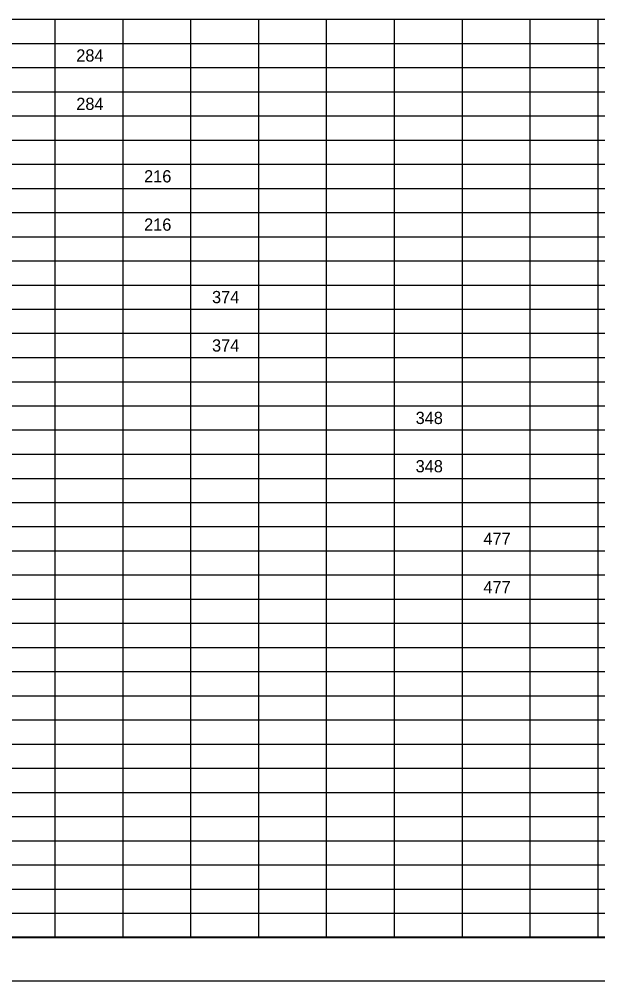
# Model space of a CAD drawing. Extents: x 0.2 to 34.2, y 0 to 22.
# Drawn here: x 6.82 to 13.45, y 0.03 to 11.04 of the extents above; entities that cross this region are included whole.
import ezdxf

# ---------------------------------------------------------------- set-up
doc = ezdxf.new("R2010")
doc.units = 0
for name, color, linetype in [('Default', 7, 'Continuous'), ('SH_Border', 7, 'Continuous'), ('SH_Cut_Line', 7, 'Continuous')]:
    doc.layers.add(name, color=color, linetype=linetype)

msp = doc.modelspace()

# ---------------------------------------------------------------- linework, layer by layer
at = {"layer": 'Default'}
for p, q in [((4.894, 11.037), (8.004, 11.037)), ((7.226, 11.037), (7.226, 10.76)), ((8.004, 11.037), (8.781, 11.037)), ((8.004, 11.037), (8.004, 10.76)), ((8.781, 11.037), (13.445, 11.037)), ((8.781, 11.037), (8.781, 10.76)), ((9.558, 11.037), (9.558, 10.76)), ((10.336, 11.037), (10.336, 10.76)), ((11.113, 11.037), (11.113, 10.76)), ((11.891, 11.037), (11.891, 10.76)), ((12.668, 11.037), (12.668, 10.76)), ((13.445, 11.037), (14.223, 11.037)), ((13.445, 11.037), (13.445, 10.76)), ((4.894, 10.76), (8.004, 10.76)), ((7.226, 10.76), (7.226, 10.483)), ((8.004, 10.76), (8.781, 10.76)), ((8.004, 10.76), (8.004, 10.483)), ((8.781, 10.76), (13.445, 10.76)), ((8.781, 10.76), (8.781, 10.483)), ((9.558, 10.76), (9.558, 10.483)), ((10.336, 10.76), (10.336, 10.483)), ((11.113, 10.76), (11.113, 10.483)), ((11.891, 10.76), (11.891, 10.483)), ((12.668, 10.76), (12.668, 10.483)), ((13.445, 10.76), (14.223, 10.76)), ((13.445, 10.76), (13.445, 10.483)), ((4.894, 10.483), (8.004, 10.483)), ((7.226, 10.483), (7.226, 10.207)), ((8.004, 10.483), (8.781, 10.483)), ((8.004, 10.483), (8.004, 10.207)), ((8.781, 10.483), (13.445, 10.483)), ((8.781, 10.483), (8.781, 10.207)), ((9.558, 10.483), (9.558, 10.207)), ((10.336, 10.483), (10.336, 10.207)), ((11.113, 10.483), (11.113, 10.207)), ((11.891, 10.483), (11.891, 10.207)), ((12.668, 10.483), (12.668, 10.207)), ((13.445, 10.483), (14.223, 10.483)), ((13.445, 10.483), (13.445, 10.207)), ((4.894, 10.207), (8.004, 10.207)), ((7.226, 10.207), (7.226, 9.93)), ((8.004, 10.207), (8.781, 10.207)), ((8.004, 10.207), (8.004, 9.93)), ((8.781, 10.207), (13.445, 10.207)), ((8.781, 10.207), (8.781, 9.93)), ((9.558, 10.207), (9.558, 9.93)), ((10.336, 10.207), (10.336, 9.93)), ((11.113, 10.207), (11.113, 9.93)), ((11.891, 10.207), (11.891, 9.93)), ((12.668, 10.207), (12.668, 9.93)), ((13.445, 10.207), (14.223, 10.207)), ((13.445, 10.207), (13.445, 9.93)), ((4.894, 9.93), (8.004, 9.93)), ((7.226, 9.93), (7.226, 9.653)), ((8.004, 9.93), (8.781, 9.93)), ((8.004, 9.93), (8.004, 9.653)), ((8.781, 9.93), (13.445, 9.93)), ((8.781, 9.93), (8.781, 9.653)), ((9.558, 9.93), (9.558, 9.653)), ((10.336, 9.93), (10.336, 9.653)), ((11.113, 9.93), (11.113, 9.653)), ((11.891, 9.93), (11.891, 9.653)), ((12.668, 9.93), (12.668, 9.653)), ((13.445, 9.93), (14.223, 9.93)), ((13.445, 9.93), (13.445, 9.653)), ((4.894, 9.653), (8.004, 9.653)), ((7.226, 9.653), (7.226, 9.377)), ((8.004, 9.653), (8.781, 9.653)), ((8.004, 9.653), (8.004, 9.377)), ((8.781, 9.653), (13.445, 9.653)), ((8.781, 9.653), (8.781, 9.377)), ((9.558, 9.653), (9.558, 9.377)), ((10.336, 9.653), (10.336, 9.377)), ((11.113, 9.653), (11.113, 9.377)), ((11.891, 9.653), (11.891, 9.377)), ((12.668, 9.653), (12.668, 9.377)), ((13.445, 9.653), (14.223, 9.653)), ((13.445, 9.653), (13.445, 9.377)), ((4.894, 9.377), (8.004, 9.377)), ((7.226, 9.377), (7.226, 9.1)), ((8.004, 9.377), (8.781, 9.377)), ((8.004, 9.377), (8.004, 9.1)), ((8.781, 9.377), (13.445, 9.377)), ((8.781, 9.377), (8.781, 9.1)), ((9.558, 9.377), (9.558, 9.1)), ((10.336, 9.377), (10.336, 9.1)), ((11.113, 9.377), (11.113, 9.1)), ((11.891, 9.377), (11.891, 9.1)), ((12.668, 9.377), (12.668, 9.1)), ((13.445, 9.377), (14.223, 9.377)), ((13.445, 9.377), (13.445, 9.1)), ((4.894, 9.1), (8.004, 9.1)), ((7.226, 9.1), (7.226, 8.823)), ((8.004, 9.1), (8.781, 9.1)), ((8.004, 9.1), (8.004, 8.823)), ((8.781, 9.1), (13.445, 9.1)), ((8.781, 9.1), (8.781, 8.823)), ((9.558, 9.1), (9.558, 8.823)), ((10.336, 9.1), (10.336, 8.823)), ((11.113, 9.1), (11.113, 8.823)), ((11.891, 9.1), (11.891, 8.823)), ((12.668, 9.1), (12.668, 8.823)), ((13.445, 9.1), (14.223, 9.1)), ((13.445, 9.1), (13.445, 8.823)), ((4.894, 8.823), (8.004, 8.823)), ((7.226, 8.823), (7.226, 8.546)), ((8.004, 8.823), (8.781, 8.823)), ((8.004, 8.823), (8.004, 8.546)), ((8.781, 8.823), (13.445, 8.823)), ((8.781, 8.823), (8.781, 8.546)), ((9.558, 8.823), (9.558, 8.546)), ((10.336, 8.823), (10.336, 8.546)), ((11.113, 8.823), (11.113, 8.546)), ((11.891, 8.823), (11.891, 8.546)), ((12.668, 8.823), (12.668, 8.546)), ((13.445, 8.823), (14.223, 8.823)), ((13.445, 8.823), (13.445, 8.546)), ((4.894, 8.546), (8.004, 8.546)), ((7.226, 8.546), (7.226, 8.27)), ((8.004, 8.546), (8.781, 8.546)), ((8.004, 8.546), (8.004, 8.27)), ((8.781, 8.546), (13.445, 8.546)), ((8.781, 8.546), (8.781, 8.27)), ((9.558, 8.546), (9.558, 8.27)), ((10.336, 8.546), (10.336, 8.27)), ((11.113, 8.546), (11.113, 8.27)), ((11.891, 8.546), (11.891, 8.27)), ((12.668, 8.546), (12.668, 8.27)), ((13.445, 8.546), (14.223, 8.546)), ((13.445, 8.546), (13.445, 8.27)), ((4.894, 8.27), (8.004, 8.27)), ((7.226, 8.27), (7.226, 7.993)), ((8.004, 8.27), (8.781, 8.27)), ((8.004, 8.27), (8.004, 7.993)), ((8.781, 8.27), (13.445, 8.27)), ((8.781, 8.27), (8.781, 7.993)), ((9.558, 8.27), (9.558, 7.993)), ((10.336, 8.27), (10.336, 7.993)), ((11.113, 8.27), (11.113, 7.993)), ((11.891, 8.27), (11.891, 7.993)), ((12.668, 8.27), (12.668, 7.993)), ((13.445, 8.27), (14.223, 8.27)), ((13.445, 8.27), (13.445, 7.993)), ((4.894, 7.993), (8.004, 7.993)), ((7.226, 7.993), (7.226, 7.716)), ((8.004, 7.993), (8.781, 7.993)), ((8.004, 7.993), (8.004, 7.716)), ((8.781, 7.993), (13.445, 7.993)), ((8.781, 7.993), (8.781, 7.716)), ((9.558, 7.993), (9.558, 7.716)), ((10.336, 7.993), (10.336, 7.716)), ((11.113, 7.993), (11.113, 7.716)), ((11.891, 7.993), (11.891, 7.716)), ((12.668, 7.993), (12.668, 7.716)), ((13.445, 7.993), (14.223, 7.993)), ((13.445, 7.993), (13.445, 7.716)), ((4.894, 7.716), (8.004, 7.716)), ((7.226, 7.716), (7.226, 7.44)), ((8.004, 7.716), (8.781, 7.716)), ((8.004, 7.716), (8.004, 7.44)), ((8.781, 7.716), (13.445, 7.716)), ((8.781, 7.716), (8.781, 7.44)), ((9.558, 7.716), (9.558, 7.44)), ((10.336, 7.716), (10.336, 7.44)), ((11.113, 7.716), (11.113, 7.44)), ((11.891, 7.716), (11.891, 7.44)), ((12.668, 7.716), (12.668, 7.44)), ((13.445, 7.716), (14.223, 7.716)), ((13.445, 7.716), (13.445, 7.44)), ((4.894, 7.44), (8.004, 7.44)), ((7.226, 7.44), (7.226, 7.163)), ((8.004, 7.44), (8.781, 7.44)), ((8.004, 7.44), (8.004, 7.163)), ((8.781, 7.44), (13.445, 7.44)), ((8.781, 7.44), (8.781, 7.163)), ((9.558, 7.44), (9.558, 7.163)), ((10.336, 7.44), (10.336, 7.163)), ((11.113, 7.44), (11.113, 7.163)), ((11.891, 7.44), (11.891, 7.163)), ((12.668, 7.44), (12.668, 7.163)), ((13.445, 7.44), (14.223, 7.44)), ((13.445, 7.44), (13.445, 7.163)), ((4.894, 7.163), (8.004, 7.163)), ((7.226, 7.163), (7.226, 6.886)), ((8.004, 7.163), (8.781, 7.163)), ((8.004, 7.163), (8.004, 6.886)), ((8.781, 7.163), (13.445, 7.163)), ((8.781, 7.163), (8.781, 6.886)), ((9.558, 7.163), (9.558, 6.886)), ((10.336, 7.163), (10.336, 6.886)), ((11.113, 7.163), (11.113, 6.886)), ((11.891, 7.163), (11.891, 6.886)), ((12.668, 7.163), (12.668, 6.886)), ((13.445, 7.163), (14.223, 7.163)), ((13.445, 7.163), (13.445, 6.886)), ((4.894, 6.886), (8.004, 6.886)), ((7.226, 6.886), (7.226, 6.609)), ((8.004, 6.886), (8.781, 6.886)), ((8.004, 6.886), (8.004, 6.609)), ((8.781, 6.886), (13.445, 6.886)), ((8.781, 6.886), (8.781, 6.609)), ((9.558, 6.886), (9.558, 6.609)), ((10.336, 6.886), (10.336, 6.609)), ((11.113, 6.886), (11.113, 6.609)), ((11.891, 6.886), (11.891, 6.609)), ((12.668, 6.886), (12.668, 6.609)), ((13.445, 6.886), (14.223, 6.886)), ((13.445, 6.886), (13.445, 6.609)), ((4.894, 6.609), (8.004, 6.609)), ((7.226, 6.609), (7.226, 6.333)), ((8.004, 6.609), (8.781, 6.609)), ((8.004, 6.609), (8.004, 6.333)), ((8.781, 6.609), (13.445, 6.609)), ((8.781, 6.609), (8.781, 6.333)), ((9.558, 6.609), (9.558, 6.333)), ((10.336, 6.609), (10.336, 6.333)), ((11.113, 6.609), (11.113, 6.333)), ((11.891, 6.609), (11.891, 6.333)), ((12.668, 6.609), (12.668, 6.333)), ((13.445, 6.609), (14.223, 6.609)), ((13.445, 6.609), (13.445, 6.333)), ((4.894, 6.333), (8.004, 6.333)), ((7.226, 6.333), (7.226, 5.779)), ((8.004, 6.333), (8.781, 6.333)), ((8.004, 6.333), (8.004, 5.779)), ((8.781, 6.333), (13.445, 6.333)), ((8.781, 6.333), (8.781, 5.779)), ((9.558, 6.333), (9.558, 5.779)), ((10.336, 6.333), (10.336, 5.779)), ((11.113, 6.333), (11.113, 5.779)), ((11.891, 6.333), (11.891, 5.779)), ((12.668, 6.333), (12.668, 5.779)), ((13.445, 6.333), (14.223, 6.333)), ((13.445, 6.333), (13.445, 5.779)), ((4.894, 6.056), (8.004, 6.056)), ((8.004, 6.056), (8.781, 6.056)), ((8.781, 6.056), (13.445, 6.056)), ((13.445, 6.056), (14.223, 6.056)), ((4.894, 5.779), (8.004, 5.779)), ((7.226, 5.779), (7.226, 5.503)), ((8.004, 5.779), (8.781, 5.779)), ((8.004, 5.779), (8.004, 5.503)), ((8.781, 5.779), (13.445, 5.779)), ((8.781, 5.779), (8.781, 5.503)), ((9.558, 5.779), (9.558, 5.503)), ((10.336, 5.779), (10.336, 5.503)), ((11.113, 5.779), (11.113, 5.503)), ((11.891, 5.779), (11.891, 5.503)), ((12.668, 5.779), (12.668, 5.503)), ((13.445, 5.779), (14.223, 5.779)), ((13.445, 5.779), (13.445, 5.503)), ((4.894, 5.503), (8.004, 5.503)), ((7.226, 5.503), (7.226, 4.396)), ((8.004, 5.503), (8.781, 5.503)), ((8.004, 5.503), (8.004, 4.396)), ((8.781, 5.503), (13.445, 5.503)), ((8.781, 5.503), (8.781, 4.396)), ((9.558, 5.503), (9.558, 4.396)), ((10.336, 5.503), (10.336, 4.396)), ((11.113, 5.503), (11.113, 4.396)), ((11.891, 5.503), (11.891, 4.396)), ((12.668, 5.503), (12.668, 4.396)), ((13.445, 5.503), (14.223, 5.503)), ((13.445, 5.503), (13.445, 4.396)), ((4.894, 5.226), (8.004, 5.226)), ((8.004, 5.226), (8.781, 5.226)), ((8.781, 5.226), (13.445, 5.226)), ((13.445, 5.226), (14.223, 5.226)), ((4.894, 4.949), (8.004, 4.949)), ((8.004, 4.949), (8.781, 4.949)), ((8.781, 4.949), (13.445, 4.949)), ((13.445, 4.949), (14.223, 4.949)), ((4.894, 4.673), (8.004, 4.673)), ((8.004, 4.673), (8.781, 4.673)), ((8.781, 4.673), (13.445, 4.673)), ((13.445, 4.673), (14.223, 4.673)), ((4.894, 4.396), (8.004, 4.396)), ((7.226, 4.396), (7.226, 4.119)), ((8.004, 4.396), (8.781, 4.396)), ((8.004, 4.396), (8.004, 4.119)), ((8.781, 4.396), (13.445, 4.396)), ((8.781, 4.396), (8.781, 4.119)), ((9.558, 4.396), (9.558, 4.119)), ((10.336, 4.396), (10.336, 4.119)), ((11.113, 4.396), (11.113, 4.119)), ((11.891, 4.396), (11.891, 4.119)), ((12.668, 4.396), (12.668, 4.119)), ((13.445, 4.396), (14.223, 4.396)), ((13.445, 4.396), (13.445, 4.119)), ((4.894, 4.119), (8.004, 4.119)), ((7.226, 4.119), (7.226, 3.012)), ((8.004, 4.119), (8.781, 4.119)), ((8.004, 4.119), (8.004, 3.012)), ((8.781, 4.119), (13.445, 4.119)), ((8.781, 4.119), (8.781, 3.012)), ((9.558, 4.119), (9.558, 3.012)), ((10.336, 4.119), (10.336, 3.012)), ((11.113, 4.119), (11.113, 3.012)), ((11.891, 4.119), (11.891, 3.012)), ((12.668, 4.119), (12.668, 3.012)), ((13.445, 4.119), (14.223, 4.119)), ((13.445, 4.119), (13.445, 3.012)), ((4.894, 3.842), (8.004, 3.842)), ((8.004, 3.842), (8.781, 3.842)), ((8.781, 3.842), (13.445, 3.842)), ((13.445, 3.842), (14.223, 3.842)), ((4.894, 3.566), (8.004, 3.566)), ((8.004, 3.566), (8.781, 3.566)), ((8.781, 3.566), (13.445, 3.566)), ((13.445, 3.566), (14.223, 3.566)), ((4.894, 3.289), (8.004, 3.289)), ((8.004, 3.289), (8.781, 3.289)), ((8.781, 3.289), (13.445, 3.289)), ((13.445, 3.289), (14.223, 3.289)), ((4.894, 3.012), (8.004, 3.012)), ((7.226, 3.012), (7.226, 2.736)), ((8.004, 3.012), (8.781, 3.012)), ((8.004, 3.012), (8.004, 2.736)), ((8.781, 3.012), (13.445, 3.012)), ((8.781, 3.012), (8.781, 2.736)), ((9.558, 3.012), (9.558, 2.736)), ((10.336, 3.012), (10.336, 2.736)), ((11.113, 3.012), (11.113, 2.736)), ((11.891, 3.012), (11.891, 2.736)), ((12.668, 3.012), (12.668, 2.736)), ((13.445, 3.012), (14.223, 3.012)), ((13.445, 3.012), (13.445, 2.736)), ((4.894, 2.736), (8.004, 2.736)), ((7.226, 2.736), (7.226, 1.629)), ((8.004, 2.736), (8.781, 2.736)), ((8.004, 2.736), (8.004, 1.629)), ((8.781, 2.736), (13.445, 2.736)), ((8.781, 2.736), (8.781, 1.629)), ((9.558, 2.736), (9.558, 1.629)), ((10.336, 2.736), (10.336, 1.629)), ((11.113, 2.736), (11.113, 1.629)), ((11.891, 2.736), (11.891, 1.629)), ((12.668, 2.736), (12.668, 1.629)), ((13.445, 2.736), (14.223, 2.736)), ((13.445, 2.736), (13.445, 1.629)), ((4.894, 2.459), (8.004, 2.459)), ((8.004, 2.459), (8.781, 2.459)), ((8.781, 2.459), (13.445, 2.459)), ((13.445, 2.459), (14.223, 2.459)), ((4.894, 2.182), (8.004, 2.182)), ((8.004, 2.182), (8.781, 2.182)), ((8.781, 2.182), (13.445, 2.182)), ((13.445, 2.182), (14.223, 2.182)), ((4.894, 1.905), (8.004, 1.905)), ((8.004, 1.905), (8.781, 1.905)), ((8.781, 1.905), (13.445, 1.905)), ((13.445, 1.905), (14.223, 1.905)), ((4.894, 1.629), (8.004, 1.629)), ((7.226, 1.629), (7.226, 1.352)), ((8.004, 1.629), (8.781, 1.629)), ((8.004, 1.629), (8.004, 1.352)), ((8.781, 1.629), (13.445, 1.629)), ((8.781, 1.629), (8.781, 1.352)), ((9.558, 1.629), (9.558, 1.352)), ((10.336, 1.629), (10.336, 1.352)), ((11.113, 1.629), (11.113, 1.352)), ((11.891, 1.629), (11.891, 1.352)), ((12.668, 1.629), (12.668, 1.352)), ((13.445, 1.629), (14.223, 1.629)), ((13.445, 1.629), (13.445, 1.352)), ((4.894, 1.352), (8.004, 1.352)), ((7.226, 1.352), (7.226, 0.522)), ((8.004, 1.352), (8.781, 1.352)), ((8.004, 1.352), (8.004, 0.522)), ((8.781, 1.352), (13.445, 1.352)), ((8.781, 1.352), (8.781, 0.522)), ((9.558, 1.352), (9.558, 0.522)), ((10.336, 1.352), (10.336, 0.522)), ((11.113, 1.352), (11.113, 0.522)), ((11.891, 1.352), (11.891, 0.522)), ((12.668, 1.352), (12.668, 0.522)), ((13.445, 1.352), (14.223, 1.352)), ((13.445, 1.352), (13.445, 0.522)), ((4.894, 1.075), (8.004, 1.075)), ((8.004, 1.075), (8.781, 1.075)), ((8.781, 1.075), (13.445, 1.075)), ((13.445, 1.075), (14.223, 1.075)), ((4.894, 0.799), (8.004, 0.799)), ((8.004, 0.799), (8.781, 0.799)), ((8.781, 0.799), (13.445, 0.799)), ((13.445, 0.799), (14.223, 0.799)), ((4.894, 0.522), (8.004, 0.522)), ((8.004, 0.522), (8.781, 0.522)), ((8.781, 0.522), (13.445, 0.522)), ((13.445, 0.522), (14.223, 0.522))]:
    msp.add_line(p, q, dxfattribs=at)
at = {"layer": 'SH_Border'}
msp.add_lwpolyline([(1.692, 21.525), (33.692, 21.525), (33.692, 0.525), (1.692, 0.525)], close=True, dxfattribs=at)
at = {"layer": 'SH_Cut_Line'}
msp.add_lwpolyline([(0.192, 0.025), (34.192, 0.025), (34.192, 22.025), (0.192, 22.025)], close=True, dxfattribs=at)

# ---------------------------------------------------------------- texts
at = {"layer": 'Default'}
for s, p in [('284', (7.472, 10.552)), ('284', (7.472, 9.998)), ('216', (8.249, 9.168)), ('216', (8.249, 8.615)), ('374', (9.027, 7.785)), ('374', (9.027, 7.231)), ('348', (11.359, 6.401)), ('348', (11.359, 5.848)), ('477', (12.136, 5.018)), ('477', (12.136, 4.464))]:
    msp.add_text(s, height=0.14, dxfattribs=at).set_placement(p)

doc.saveas('drawing.dxf')
